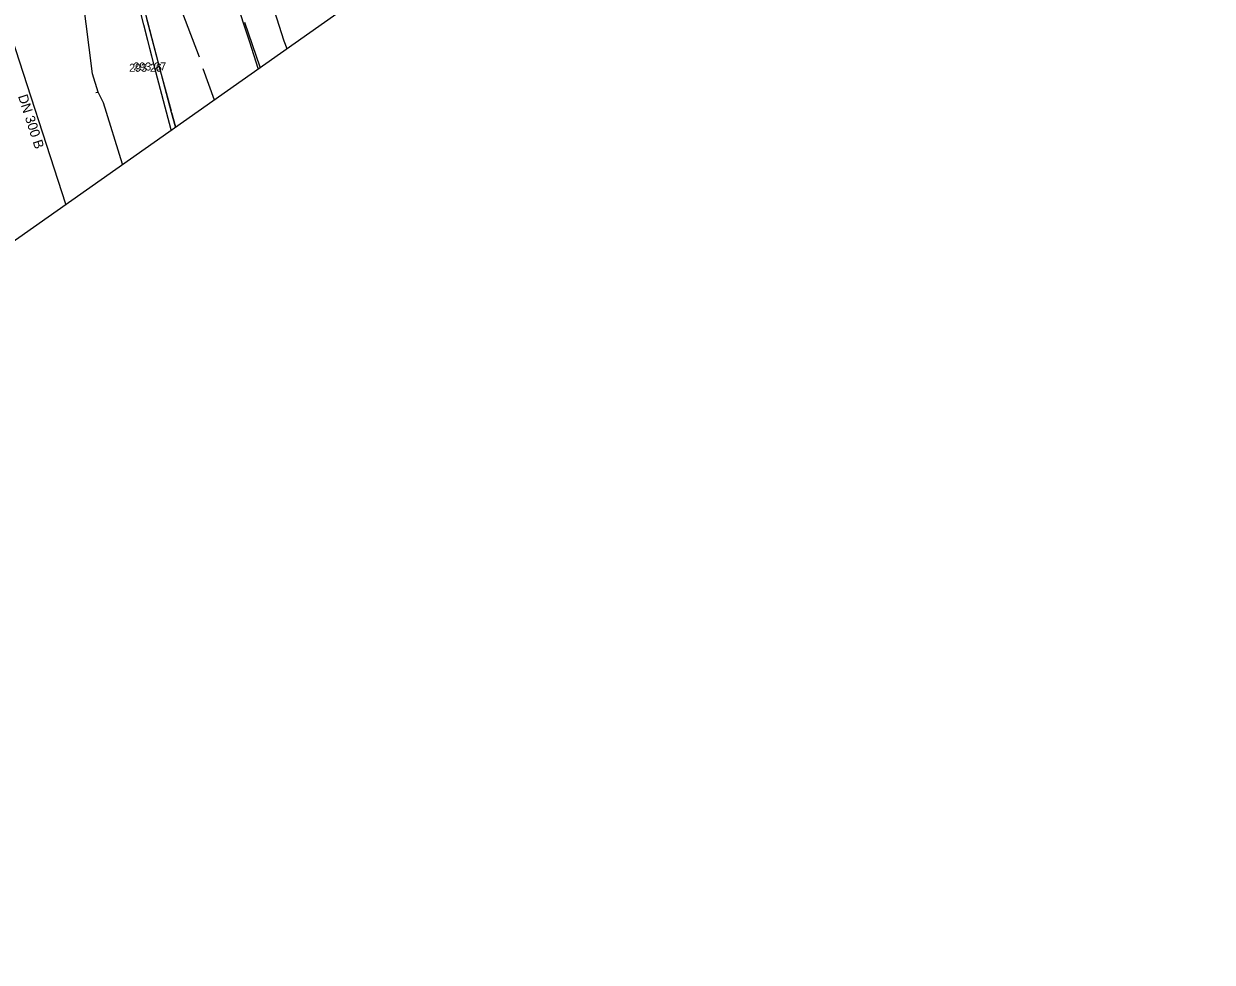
# Model space of a CAD drawing. Extents: x -492431 to -49223, y -1127123 to -112687.
# Drawn here: x -492244.4 to -492133, y -1127122.9 to -1127035 of the extents above; entities that cross this region are included whole.
import ezdxf

# ---------------------------------------------------------------- set-up
doc = ezdxf.new("R2010")
doc.units = 0
for name, color, linetype in [('Vrstva 1', 7, 'Continuous'), ('Vrstva 11', 7, 'Continuous'), ('Vrstva 15', 7, 'Continuous'), ('Vrstva 19', 7, 'Continuous'), ('Vrstva 26', 7, 'Continuous'), ('Vrstva 45', 7, 'Continuous'), ('Vrstva 49', 7, 'Continuous'), ('Vrstva 5', 7, 'Continuous')]:
    doc.layers.add(name, color=color, linetype=linetype)

msp = doc.modelspace()

# ---------------------------------------------------------------- linework, layer by layer
at = {"layer": 'Vrstva 1'}
msp.add_lwpolyline([(-492341.24, -1127122.91), (-492133.03, -1126976.26), (-492272.7, -1126862.46), (-492313.78, -1126867.2)], dxfattribs=at)
at = {"layer": 'Vrstva 11'}
msp.add_lwpolyline([(-492222.22, -1127039.08), (-492223.65, -1127034.91)], dxfattribs=at)
at = {"layer": 'Vrstva 15'}
msp.add_line((-492240.43, -1127051.91), (-492245.82, -1127035.24), dxfattribs=at)
at = {"layer": 'Vrstva 26'}
for p, q in [((-492223.19, -1127036.73), (-492226.04, -1127027.94)), ((-492237.92, -1127039.69), (-492238.96, -1127031.54)), ((-492222.4, -1127039.21), (-492223.19, -1127036.73)), ((-492237.41, -1127041.41), (-492237.92, -1127039.69)), ((-492237.61, -1127041.46), (-492237.41, -1127041.41)), ((-492236.91, -1127042.43), (-492237.41, -1127041.41)), ((-492235.13, -1127048.17), (-492236.91, -1127042.43))]:
    msp.add_line(p, q, dxfattribs=at)
at = {"layer": 'Vrstva 45'}
for p, q in [((-492233.73, -1127022.79), (-492227.95, -1127038.1)), ((-492234.6, -1127027.76), (-492231.6, -1127039.39)), ((-492233.13, -1127035.1), (-492234.04, -1127031.55)), ((-492232, -1127039.51), (-492233.13, -1127035.09)), ((-492232, -1127039.51), (-492233.13, -1127035.1)), ((-492230.52, -1127043.32), (-492232.85, -1127034.55)), ((-492232, -1127039.51), (-492232, -1127039.51)), ((-492230.55, -1127044.95), (-492232, -1127039.51)), ((-492230.55, -1127044.95), (-492232, -1127039.51)), ((-492231.6, -1127039.39), (-492231.6, -1127039.39)), ((-492231.6, -1127039.39), (-492230.56, -1127043.17)), ((-492227.6, -1127039.21), (-492226.54, -1127042.13)), ((-492230.52, -1127043.32), (-492230.15, -1127044.67)), ((-492230.15, -1127044.67), (-492230.52, -1127043.32))]:
    msp.add_line(p, q, dxfattribs=at)
at = {"layer": 'Vrstva 5'}
msp.add_lwpolyline([(-492224.58, -1127022.72), (-492222.69, -1127028.14), (-492220.01, -1127036.6), (-492219.73, -1127037.33)], dxfattribs=at)

# ---------------------------------------------------------------- texts
at = {"layer": 'Vrstva 19'}
msp.add_text('DN 300 B', height=0.91, rotation=287.9199, dxfattribs=at).set_placement((-492244.92, -1127041.8))
at = {"layer": 'Vrstva 49'}
for s, p in [('293 26 ', (-492234.5, -1127039.51)), ('293 27 ', (-492234.1, -1127039.39))]:
    msp.add_text(s, height=0.75, dxfattribs=at).set_placement(p)

doc.saveas('drawing.dxf')
